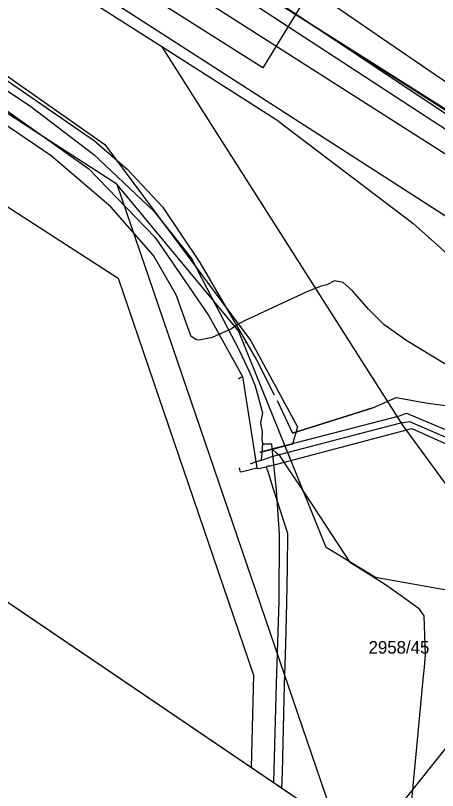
# Model space of a CAD drawing. Extents: x -621145 to -620023, y -1122866 to -1121971.
# Drawn here: x -620574.9 to -620524.6, y -1122625.8 to -1122533.2 of the extents above; entities that cross this region are included whole.
import ezdxf

# ---------------------------------------------------------------- set-up
doc = ezdxf.new("R2010")
doc.units = 0
for name, color, linetype in [('CETIN', 7, 'Continuous'), ('GasNet', 7, 'Continuous'), ('itself', 7, 'Continuous'), ('PS 06-14-01_trasa_sdělovací_nové', 7, 'Continuous'), ('RÁMY', 7, 'Continuous'), ('SEE', 7, 'Continuous'), ('SSZT', 7, 'Continuous'), ('VAS stoka', 7, 'Continuous'), ('VAS vodovod', 7, 'Continuous'), ('Vrstva 1', 7, 'Continuous'), ('Vrstva 53', 7, 'Continuous'), ('Vrstva 55', 7, 'Continuous'), ('Vrstva 56', 7, 'Continuous'), ('Vrstva 57', 7, 'Continuous'), ('Vrstva 62', 7, 'Continuous')]:
    doc.layers.add(name, color=color, linetype=linetype)

msp = doc.modelspace()

# ---------------------------------------------------------------- linework, layer by layer
at = {"layer": 'CETIN'}
for points in [[(-620646.43, -1122495.05), (-620612.92, -1122515.84), (-620612.23, -1122516.26), (-620607.1, -1122519.79), (-620583.87, -1122535.51), (-620565.48, -1122548.17), (-620561.56, -1122551.58), (-620557.36, -1122556.05), (-620552.9, -1122562.72), (-620546.13, -1122574.35), (-620544.028, -1122578.529)], [(-620547.37, -1122572.22), (-620547.523, -1122572.289)], [(-620543.69, -1122579.2), (-620541.87, -1122583.1), (-620532.27, -1122580.05), (-620529.5, -1122578.82), (-620525.69, -1122579.49), (-620520.52, -1122580.2), (-620515.66, -1122580.54), (-620511.76, -1122581.44), (-620509.68, -1122582.26), (-620506.2, -1122582.41), (-620494.32, -1122581.82), (-620491.48, -1122581.44), (-620483.44, -1122578.57)], [(-620532.27, -1122580.05), (-620541.87, -1122583.1)]]:
    msp.add_lwpolyline(points, dxfattribs=at)
at = {"layer": 'GasNet'}
for points in [[(-620586.31, -1122535.34), (-620573.22, -1122543.96), (-620565.55, -1122549.81), (-620558.39, -1122556.56), (-620553.9, -1122562.25), (-620551.49, -1122566.93), (-620548.21, -1122573.19), (-620546.94, -1122575.89), (-620546.29, -1122577.44), (-620545.44, -1122580.66), (-620545.67, -1122581.84), (-620545.49, -1122582.92), (-620545.5, -1122583.84), (-620545.45, -1122584.35), (-620545.55, -1122585.95), (-620545.62, -1122586.36)], [(-620545.62, -1122586.36), (-620544.33, -1122585.86), (-620529.1, -1122581.91), (-620527.88, -1122581.68), (-620501.79, -1122593.01), (-620500.52, -1122592.53), (-620484.13, -1122585.56), (-620478.57, -1122583.14), (-620474.2, -1122586.82), (-620449.91, -1122606.86), (-620450.02, -1122607.5), (-620458.5, -1122620.02), (-620458.8, -1122620.62), (-620432.06, -1122640.49), (-620425.64, -1122643.91), (-620417.98, -1122647.99), (-620389.11, -1122672.47), (-620361.34, -1122696.38), (-620351.16, -1122708.72), (-620351, -1122709.02), (-620350.83, -1122709.39), (-620350.53, -1122710.79), (-620349.5, -1122710.44), (-620336.68, -1122702.48)], [(-620545.45, -1122584.35), (-620544.34, -1122584.36), (-620544.31, -1122584.94), (-620543.79, -1122589.85), (-620543.45, -1122595.16)], [(-620545.62, -1122586.36), (-620546.42, -1122586.61), (-620546.89, -1122586.78)], [(-620543.45, -1122595.16), (-620543.47, -1122603.15), (-620543.79, -1122613), (-620544.07, -1122623.3), (-620544.13, -1122624.831)]]:
    msp.add_lwpolyline(points, dxfattribs=at)
at = {"layer": 'itself'}
msp.add_lwpolyline([(-620523.686, -1122574.822), (-620528.196, -1122572.082), (-620530.966, -1122570.132), (-620532.766, -1122568.302), (-620534.705, -1122566.112), (-620535.816, -1122565.082), (-620536.826, -1122564.912), (-620537.766, -1122565.362), (-620538.416, -1122565.552), (-620540.126, -1122566.232), (-620547.566, -1122569.682), (-620548.366, -1122570.132), (-620549.136, -1122570.642), (-620551.436, -1122571.662), (-620553.016, -1122571.982), (-620553.026, -1122571.982), (-620553.296, -1122571.942), (-620553.946, -1122571.562), (-620554.176, -1122570.902), (-620555.716, -1122566.582), (-620558.436, -1122561.862), (-620563.546, -1122556.052), (-620570.666, -1122549.952), (-620584.476, -1122540.562)], dxfattribs=at)
at = {"layer": 'PS 06-14-01_trasa_sdělovací_nové'}
msp.add_lwpolyline([(-620248.321, -1122722.765), (-620259.889, -1122713.575), (-620277.711, -1122700.887), (-620282.346, -1122705.302), (-620297.82, -1122689.49), (-620310.815, -1122680.061), (-620322.228, -1122672.322), (-620343.182, -1122658.459), (-620368.499, -1122642.897), (-620411.557, -1122614.916), (-620456.111, -1122587.123), (-620544.953, -1122530.859), (-620538.89, -1122521.208), (-620538.89, -1122521.208), (-620538.89, -1122521.208)], dxfattribs=at)
at = {"layer": 'RÁMY'}
for points in [[(-621061.558, -1122093.918), (-620106.075, -1122742.822), (-620189.505, -1122865.67), (-621144.989, -1122216.766)], [(-620887.834, -1122211.901), (-620106.075, -1122742.822), (-620189.505, -1122865.67), (-620971.264, -1122334.748)]]:
    msp.add_lwpolyline(points, close=True, dxfattribs=at)
at = {"layer": 'SEE'}
msp.add_lwpolyline([(-620244.518, -1122694.296), (-620246.547, -1122692.66), (-620267.469, -1122718.6), (-620268.222, -1122719.534), (-620284.407, -1122704.62), (-620304.333, -1122686.26), (-620309.55, -1122681.453), (-620327.714, -1122669.483), (-620362.834, -1122646.339), (-620390.254, -1122629.02), (-620411.934, -1122614.961), (-620423.125, -1122608.012), (-620468.337, -1122579.91), (-620468.337, -1122579.91), (-620460.94, -1122568.103), (-620517.418, -1122533.032), (-620535.001, -1122522.477), (-620545.407, -1122539.454), (-620611.375, -1122497.696)], dxfattribs=at)
at = {"layer": 'SSZT'}
msp.add_lwpolyline([(-620879.238, -1122313.316), (-620842.993, -1122336.61), (-620835.049, -1122343.251), (-620812.66, -1122358.949), (-620764.902, -1122389.752), (-620688.594, -1122438.969), (-620596.981, -1122496.725), (-620576.744, -1122509.484), (-620506.746, -1122556.123), (-620447.293, -1122593.619), (-620363.271, -1122647.563), (-620313.966, -1122679.218), (-620306.51, -1122669.289), (-620273.137, -1122696.274), (-620258.422, -1122709.142), (-620248.072, -1122696.094)], dxfattribs=at)
at = {"layer": 'VAS stoka'}
for points in [[(-620781.72, -1122408.87), (-620776.69, -1122412.14), (-620774.2, -1122412.02), (-620772.21, -1122412.95), (-620766.77, -1122415.95), (-620758.11, -1122421.89), (-620737.16, -1122435.39), (-620726.71, -1122442.22), (-620705.9, -1122455.54), (-620681.71, -1122471.08), (-620665.23, -1122481.83), (-620655.606, -1122488.117), (-620638.12, -1122499.53), (-620609.99, -1122517.38), (-620585.88, -1122533.44), (-620564.23, -1122548.6), (-620546.83, -1122572.05), (-620541.253, -1122582.331), (-620541.865, -1122584.423), (-620543.527, -1122584.845), (-620544.25, -1122585.029)], [(-620544.25, -1122585.029), (-620545.68, -1122585.41), (-620545.7, -1122585.34), (-620544.74, -1122585.09), (-620529.09, -1122581.01), (-620528.27, -1122580.72), (-620501.26, -1122592.08), (-620484.32, -1122584.76), (-620478.68, -1122582.19), (-620475.52, -1122584.33), (-620473.62, -1122582.33), (-620454.46, -1122552.49), (-620449.28, -1122555.81), (-620438.79, -1122557.25), (-620438.13, -1122557.28)], [(-620528.562, -1122635.404), (-620528.278, -1122633.029), (-620527.953, -1122629.96), (-620527.627, -1122626.89), (-620527.309, -1122623.538), (-620526.991, -1122620.187), (-620526.62, -1122616.34), (-620526.248, -1122612.494), (-620526.118, -1122611.034), (-620525.987, -1122609.574), (-620526.074, -1122607.233), (-620526.16, -1122604.893), (-620526.431, -1122604.504), (-620526.702, -1122604.116), (-620528.728, -1122602.652), (-620530.754, -1122601.188), (-620532.839, -1122599.89), (-620534.923, -1122598.593), (-620537.947, -1122593.969), (-620540.971, -1122589.345), (-620542.157, -1122587.591), (-620543.343, -1122585.837), (-620543.797, -1122585.433), (-620544.25, -1122585.029)]]:
    msp.add_lwpolyline(points, dxfattribs=at)
at = {"layer": 'VAS vodovod'}
for points in [[(-620783.05, -1122410.36), (-620779.49, -1122412.44), (-620776.82, -1122413.57), (-620766.15, -1122419), (-620759.23, -1122423.16), (-620738.05, -1122436.88), (-620666.7, -1122483.31), (-620630.69, -1122506.76), (-620611.44, -1122519.95), (-620587.32, -1122536.52), (-620566.14, -1122551.51), (-620558.22, -1122559.71), (-620551.85, -1122569.08), (-620547.83, -1122576.32), (-620546.15, -1122586.98), (-620546.105, -1122587.264)], [(-620548.28, -1122576.61), (-620548.08, -1122576.43), (-620547.83, -1122576.32)], [(-620544.967, -1122587.097), (-620544.863, -1122587.05), (-620544.76, -1122587.004), (-620544.537, -1122586.974), (-620544.315, -1122586.943), (-620527.61, -1122582.527), (-620502.02, -1122594.032), (-620500.778, -1122593.455), (-620500.104, -1122593.231), (-620483.666, -1122586.375), (-620481.327, -1122585.405), (-620479.583, -1122584.864), (-620478.408, -1122584.641), (-620477.754, -1122585.105), (-620476.869, -1122585.61)], [(-620546.105, -1122587.264), (-620547.819, -1122587.714), (-620548.065, -1122587.764), (-620548.143, -1122587.449), (-620548.194, -1122587.245)], [(-620546.105, -1122587.264), (-620545.745, -1122587.294), (-620545.542, -1122587.243), (-620545.338, -1122587.191), (-620545.153, -1122587.144), (-620544.967, -1122587.097)], [(-620544.967, -1122587.097), (-620544.948, -1122587.248), (-620544.929, -1122587.398), (-620544.871, -1122587.521), (-620544.812, -1122587.644), (-620544.235, -1122589.495), (-620543.658, -1122591.345), (-620543.047, -1122593.188), (-620542.435, -1122595.031), (-620542.492, -1122599.187), (-620542.549, -1122603.343), (-620542.689, -1122608.247), (-620542.829, -1122613.151), (-620542.948, -1122618.376), (-620543.067, -1122623.6), (-620543.149, -1122625.498)]]:
    msp.add_lwpolyline(points, dxfattribs=at)
at = {"layer": 'Vrstva 1'}
for points in [[(-620582.331, -1122501.971), (-620566.971, -1122511.728), (-620560.029, -1122516.238), (-620551.869, -1122521.685), (-620548.619, -1122523.887), (-620542.396, -1122528.151), (-620538.064, -1122531.158), (-620531.122, -1122535.952), (-620524.966, -1122540.177), (-620518.618, -1122544.427), (-620513.645, -1122547.697), (-620506.55, -1122552.247), (-620496.304, -1122558.659), (-620480.231, -1122568.734), (-620462.233, -1122580.043), (-620447.551, -1122589.267), (-620431.6, -1122599.485), (-620414.27, -1122610.379), (-620398.172, -1122620.479), (-620378.269, -1122633.015), (-620362.958, -1122642.66), (-620347.616, -1122652.305), (-620342.456, -1122655.575)], [(-620456.111, -1122587.123), (-620500.015, -1122559.595), (-620522.22, -1122545.451), (-620544.953, -1122530.859)]]:
    msp.add_lwpolyline(points, dxfattribs=at)
at = {"layer": 'Vrstva 53'}
msp.add_line((-620521.41, -1122548.27), (-620545.92, -1122532.26), dxfattribs=at)
at = {"layer": 'Vrstva 55'}
for p, q in [((-620557.45, -1122536.96), (-620684.91, -1122455.63)), ((-620511.29, -1122557.64), (-620587.17, -1122509.18)), ((-620521.41, -1122548.27), (-620545.92, -1122532.26)), ((-620557.45, -1122536.96), (-620551.15, -1122546.87)), ((-620543.5, -1122545.86), (-620557.45, -1122536.96)), ((-620543.5, -1122545.86), (-620527.5, -1122558.02)), ((-620551.15, -1122546.87), (-620547.19, -1122553.1)), ((-620548.28, -1122570.88), (-620562.8, -1122553.35)), ((-620562.8, -1122553.35), (-620536.709, -1122629.871)), ((-620547.19, -1122553.1), (-620536.04, -1122570.64)), ((-620519.77, -1122564.93), (-620527.5, -1122558.02)), ((-620537.83, -1122596.73), (-620548.28, -1122570.88)), ((-620536.04, -1122570.64), (-620528.72, -1122582.15)), ((-620528.72, -1122582.15), (-620521.17, -1122592.53)), ((-620531.96, -1122600.32), (-620537.83, -1122596.73)), ((-620510.44, -1122604.21), (-620531.96, -1122600.32)), ((-620532.903, -1122632.456), (-620510.44, -1122604.21))]:
    msp.add_line(p, q, dxfattribs=at)
for points in [[(-620562.8, -1122553.35), (-620572.54, -1122547.06), (-620576.58, -1122544.45)], [(-620581.67, -1122552.32), (-620562.67, -1122564.59), (-620546.5, -1122612), (-620546.777, -1122623.034)]]:
    msp.add_lwpolyline(points, dxfattribs=at)
at = {"layer": 'Vrstva 56'}
msp.add_line((-620504.94, -1122569.2), (-620570.69, -1122526.84), dxfattribs=at)
at = {"layer": 'Vrstva 62'}
for p, q in [((-620530.738, -1122535.331), (-620530.738, -1122535.331)), ((-620531.506, -1122536.573), (-620531.506, -1122536.573)), ((-620524.588, -1122539.569), (-620524.588, -1122539.569)), ((-620525.343, -1122540.785), (-620525.343, -1122540.785))]:
    msp.add_line(p, q, dxfattribs=at)

# ---------------------------------------------------------------- texts
at = {"layer": 'Vrstva 57'}
msp.add_text('2958/45', height=1.5, dxfattribs=at).set_placement((-620532.775, -1122609.42))

doc.saveas('drawing.dxf')
